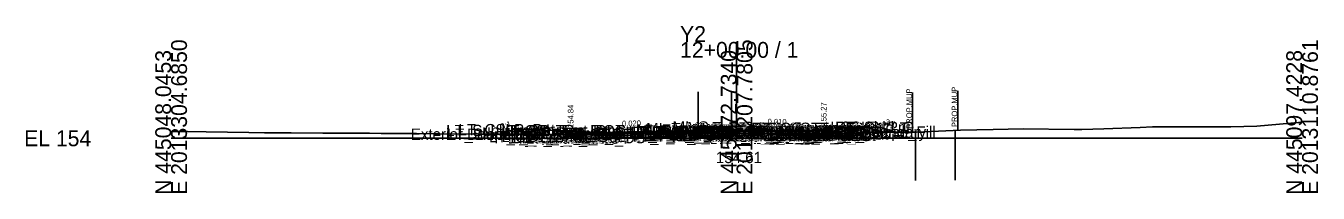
# Model space of a CAD drawing. Extents: x -26 to 203, y -10 to 6017.
# Drawn here: x -25.7 to 202.8, y 3990.3 to 4019.9 of the extents above; entities that cross this region are included whole.
import ezdxf

# ---------------------------------------------------------------- set-up
doc = ezdxf.new("R2010")
doc.units = 0
for name, color, linetype in [('Default', 7, 'Continuous'), ('Exist Cross Section Cell', 7, 'Continuous'), ('Exist XS Center Line Elevation Label', 7, 'Continuous'), ('Exist XS Ground Line', 7, 'Continuous'), ('Prop CMT Conc Surface', 7, 'Continuous'), ('Prop CMT Concrete Structures', 7, 'Continuous'), ('Prop CMT Pvmt Course 1', 7, 'Continuous'), ('Prop CMT Pvmt Course 1 CG', 7, 'Continuous'), ('Prop CMT Pvmt Course 1 Wedge', 7, 'Continuous'), ('Prop CMT Pvmt Course 2', 7, 'Continuous'), ('Prop CMT Pvmt Course 2 Wedge', 7, 'Continuous'), ('Prop CMT Pvmt Course 3', 7, 'Continuous'), ('Prop CMT Pvmt Course 3 Wedge', 7, 'Continuous'), ('Prop CMT Pvmt Surface', 7, 'Continuous'), ('Prop CMT Pvmt Wedge Surface 1', 7, 'Continuous'), ('Prop CMT Pvmt Wedge Surface 2', 7, 'Continuous'), ('Prop CMT Pvmt Wedge Surface 3', 7, 'Continuous'), ('Prop CMT Slope Grass', 7, 'Continuous'), ('Prop CMT Subgrade Earthwork', 7, 'Continuous'), ('Prop XS Earthwork Shape', 7, 'Continuous'), ('Prop XS Hydro Elevations', 7, 'Continuous'), ('Prop XS Label Text', 7, 'Continuous'), ('Prop XS SE Text', 7, 'Continuous'), ('Prop XS Side Slope Text', 7, 'Continuous'), ('Scratch_Level_0', 7, 'Continuous'), ('Scratch_Level_1', 7, 'Continuous'), ('Scratch_Level_3', 7, 'Continuous')]:
    doc.layers.add(name, color=color, linetype=linetype)

msp = doc.modelspace()

# ---------------------------------------------------------------- linework, layer by layer
at = {"layer": 'Exist Cross Section Cell'}
for p, q in [((100, 4000), (100, 4017.03)), ((0, 4000), (100, 4000)), ((100, 4000), (200, 4000))]:
    msp.add_line(p, q, dxfattribs=at)
at = {"layer": 'Exist XS Ground Line'}
msp.add_lwpolyline([(0, 4001.22), (2.89, 4001.18), (6.21, 4001.13), (13.76, 4001.04), (16.53, 4000.98), (21.2, 4000.95), (26.85, 4000.89), (35.05, 4000.88), (37.17, 4000.87), (43.39, 4000.82), (46.66, 4000.81), (47.5, 4000.81), (54.89, 4000.72), (66.1, 4000.74), (69.73, 4000.66), (70.84, 4000.67), (77.18, 4000.71), (83.2, 4000.83), (93.77, 4000.89), (95.2, 4000.9), (95.76, 4000.83), (97.2, 4000.62), (98.31, 4000.62), (100, 4000.61), (107.08, 4000.57), (112.01, 4000.56), (117.01, 4000.56), (118.46, 4000.76), (118.81, 4000.81), (120.45, 4000.9), (125.07, 4001.11), (127.67, 4001.11), (131.82, 4001.11), (139.6, 4001.42), (145.36, 4001.54), (150.7, 4001.69), (159.69, 4001.55), (161.02, 4001.56), (164.92, 4001.68), (171.34, 4001.92), (173.54, 4002.02), (181.66, 4002.04), (187.39, 4002.03), (191.99, 4002.17), (200, 4002.88)], dxfattribs=at)
at = {"layer": 'Prop CMT Conc Surface'}
for points in [[(115.4, 4001.27), (115.41, 4001.77), (115.91, 4001.77)], [(66.15, 4001.43), (61.15, 4001.53)], [(70.65, 4000.84), (70.65, 4001.34), (70.15, 4001.34)], [(70.65, 4000.84), (70.65, 4001.34), (70.15, 4001.34)], [(72.65, 4000.96), (70.65, 4000.84)], [(113.4, 4001.37), (115.4, 4001.27)]]:
    msp.add_lwpolyline(points, dxfattribs=at)
at = {"layer": 'Prop CMT Concrete Structures'}
for p, q in [((93.99, 4001.78), (93.24, 4001.53)), ((98.33, 4001.93), (93.99, 4001.78)), ((99.08, 4001.68), (98.33, 4001.93)), ((99.09, 4001.51), (99.08, 4001.68)), ((93.24, 4001.53), (93.23, 4001.36))]:
    msp.add_line(p, q, dxfattribs=at)
for points in [[(113.4, 4001.37), (115.4, 4001.27), (115.41, 4001.77), (115.91, 4001.77)], [(115.91, 4001.77), (115.9, 4000.76), (113.4, 4000.79)], [(61.15, 4001.19), (61.15, 4001.53)], [(61.15, 4001.53), (66.15, 4001.43)], [(66.15, 4001.09), (61.15, 4001.19)], [(66.15, 4001.43), (66.15, 4001.09)], [(72.65, 4000.96), (70.65, 4000.84), (70.65, 4001.34), (70.15, 4001.34)], [(70.15, 4001.34), (70.15, 4000.32), (72.65, 4000.37)], [(72.65, 4000.37), (72.65, 4000.96)], [(93.23, 4001.36), (99.09, 4001.51)], [(113.4, 4000.79), (113.4, 4001.37)]]:
    msp.add_lwpolyline(points, dxfattribs=at)
at = {"layer": 'Prop CMT Pvmt Course 1'}
for points in [[(93.23, 4001.37), (72.65, 4000.96)], [(72.65, 4000.71), (93.23, 4001.12)], [(72.65, 4000.96), (72.65, 4000.71)], [(93.23, 4001.36), (99.09, 4001.51)], [(93.23, 4001.11), (93.23, 4001.36)], [(93.23, 4001.11), (93.23, 4001.36)], [(99.09, 4001.26), (93.23, 4001.11)], [(93.23, 4001.24), (93.23, 4001.11), (93.23, 4001.11)], [(99.09, 4001.51), (113.4, 4001.37)], [(99.09, 4001.26), (99.09, 4001.51)], [(99.09, 4001.51), (99.09, 4001.26)], [(112.4, 4001.25), (99.09, 4001.39)], [(99.09, 4001.39), (99.09, 4001.26), (99.09, 4001.26)], [(112.4, 4001.13), (112.4, 4001.25)], [(113.4, 4001.12), (112.4, 4001.13)], [(113.4, 4001.37), (113.4, 4001.12)]]:
    msp.add_lwpolyline(points, dxfattribs=at)
at = {"layer": 'Prop CMT Pvmt Course 1 CG'}
for points in [[(72.65, 4000.37), (69.65, 4000.31), (69.31, 3999.97)], [(69.31, 3999.97), (72.65, 4000.04)], [(72.65, 4000.12), (72.65, 4000.37)], [(113.4, 4000.79), (116.4, 4000.76), (116.74, 4000.42)], [(113.4, 4000.54), (113.4, 4000.79)], [(116.74, 4000.42), (113.4, 4000.45)]]:
    msp.add_lwpolyline(points, dxfattribs=at)
at = {"layer": 'Prop CMT Pvmt Course 1 Wedge'}
for points in [[(99.09, 4001.26), (99.09, 4001.39)], [(112.4, 4001.13), (112.01, 4001.13), (107.08, 4001.18), (99.09, 4001.26)], [(100.8, 4001.37), (107.08, 4001.31), (112.01, 4001.26), (112.4, 4001.25)], [(112.4, 4001.25), (112.4, 4001.13)]]:
    msp.add_lwpolyline(points, dxfattribs=at)
at = {"layer": 'Prop CMT Pvmt Course 2'}
for points in [[(93.23, 4001.12), (72.65, 4000.71)], [(72.65, 4000.37), (93.23, 4000.79)], [(72.65, 4000.71), (72.65, 4000.37)], [(93.23, 4001.11), (99.09, 4001.26)], [(93.23, 4000.78), (93.23, 4001.11)], [(99.09, 4000.93), (93.23, 4000.78)], [(99.09, 4001.26), (99.09, 4000.93)], [(112.4, 4000.8), (112.4, 4001.13)], [(112.4, 4001.13), (113.4, 4001.12)], [(113.4, 4000.79), (112.4, 4000.8)], [(113.4, 4001.12), (113.4, 4000.79)]]:
    msp.add_lwpolyline(points, dxfattribs=at)
at = {"layer": 'Prop CMT Pvmt Course 2 Wedge'}
for points in [[(99.09, 4001.26), (107.08, 4001.18), (112.01, 4001.13), (112.4, 4001.13)], [(99.09, 4000.93), (99.09, 4001.26)], [(112.4, 4000.8), (112.01, 4000.8), (107.08, 4000.85), (99.09, 4000.93)], [(112.4, 4001.13), (112.4, 4000.8)]]:
    msp.add_lwpolyline(points, dxfattribs=at)
at = {"layer": 'Prop CMT Pvmt Course 3'}
for points in [[(93.23, 4000.79), (72.65, 4000.37)], [(72.65, 4000.04), (93.23, 4000.45)], [(72.65, 4000.37), (72.65, 4000.04)], [(93.23, 4000.78), (99.09, 4000.93)], [(93.23, 4000.45), (93.23, 4000.78)], [(97.2, 4000.52), (93.23, 4000.45)], [(112.4, 4000.8), (113.4, 4000.79)], [(112.4, 4000.46), (112.4, 4000.8)], [(113.4, 4000.45), (112.4, 4000.46)], [(113.4, 4000.79), (113.4, 4000.45)]]:
    msp.add_lwpolyline(points, dxfattribs=at)
at = {"layer": 'Prop CMT Pvmt Course 3 Wedge'}
for points in [[(99.09, 4000.93), (107.08, 4000.85), (112.01, 4000.8), (112.4, 4000.8)], [(112.4, 4000.56), (112.01, 4000.56), (107.08, 4000.57), (100.8, 4000.61)], [(112.4, 4000.8), (112.4, 4000.56)]]:
    msp.add_lwpolyline(points, dxfattribs=at)
at = {"layer": 'Prop CMT Pvmt Surface'}
for points in [[(93.23, 4001.37), (72.65, 4000.96)], [(93.23, 4001.36), (99.09, 4001.51)], [(99.09, 4001.51), (113.4, 4001.37)]]:
    msp.add_lwpolyline(points, dxfattribs=at)
at = {"layer": 'Prop CMT Pvmt Wedge Surface 1'}
for points in [[(99.09, 4001.51), (99.09, 4001.26), (99.09, 4001.26), (99.09, 4001.39)], [(100.8, 4001.37), (112.4, 4001.25)], [(112.4, 4001.25), (112.4, 4001.13)], [(112.4, 4001.13), (113.4, 4001.12)], [(113.4, 4001.12), (113.4, 4001.37)]]:
    msp.add_lwpolyline(points, dxfattribs=at)
at = {"layer": 'Prop CMT Pvmt Wedge Surface 2'}
for points in [[(99.09, 4001.51), (99.09, 4001.26)], [(99.09, 4001.26), (113.4, 4001.12)], [(113.4, 4001.12), (113.4, 4001.37)]]:
    msp.add_lwpolyline(points, dxfattribs=at)
at = {"layer": 'Prop CMT Pvmt Wedge Surface 3'}
for points in [[(99.09, 4001.51), (99.09, 4000.93)], [(99.09, 4000.93), (113.4, 4000.79)], [(113.4, 4000.79), (113.4, 4001.37)]]:
    msp.add_lwpolyline(points, dxfattribs=at)
at = {"layer": 'Prop CMT Slope Grass'}
for points in [[(115.91, 4001.77), (124.91, 4001.95)], [(124.91, 4001.95), (125.41, 4001.96), (127.96, 4001.11)], [(70.15, 4001.34), (60.65, 4001.53), (58.24, 4000.72)]]:
    msp.add_lwpolyline(points, dxfattribs=at)
at = {"layer": 'Prop CMT Subgrade Earthwork'}
msp.add_line((97.2, 4000.62), (97.2, 4000.52), dxfattribs=at)
for points in [[(113.4, 4000.45), (116.74, 4000.42), (118.14, 4001.81)], [(72.65, 4000.04), (69.31, 3999.97), (67.9, 4001.38)], [(93.23, 4000.45), (72.65, 4000.04)], [(93.23, 4000.45), (97.2, 4000.52)], [(112.4, 4000.46), (112.39, 4000.56)], [(112.4, 4000.46), (113.4, 4000.45)]]:
    msp.add_lwpolyline(points, dxfattribs=at)
at = {"layer": 'Prop XS Earthwork Shape'}
for points in [[(116.89, 4000.56), (118.14, 4001.81), (124.91, 4001.95), (125.41, 4001.96), (127.96, 4001.11), (127.67, 4001.11), (125.07, 4001.11), (120.45, 4000.9), (118.81, 4000.81), (118.46, 4000.76), (117.01, 4000.56)], [(116.89, 4000.56), (118.14, 4001.81), (124.91, 4001.95), (125.41, 4001.96), (127.96, 4001.11), (127.67, 4001.11), (125.07, 4001.11), (120.45, 4000.9), (118.81, 4000.81), (118.46, 4000.76), (117.01, 4000.56)], [(125.41, 4001.96), (127.96, 4001.11), (127.67, 4001.11), (125.07, 4001.11), (120.45, 4000.9), (118.81, 4000.81), (118.46, 4000.76), (117.01, 4000.56), (116.89, 4000.56), (118.14, 4001.81), (124.91, 4001.95)], [(116.89, 4000.56), (118.14, 4001.81), (124.91, 4001.95), (125.41, 4001.96), (127.96, 4001.11), (127.67, 4001.11), (125.07, 4001.11), (120.45, 4000.9), (118.81, 4000.81), (118.46, 4000.76), (117.01, 4000.56)], [(68.6, 4000.68), (67.9, 4001.38), (60.65, 4001.53), (58.24, 4000.72), (66.1, 4000.74)], [(68.6, 4000.68), (67.9, 4001.38), (60.65, 4001.53), (58.24, 4000.72), (66.1, 4000.74)], [(68.6, 4000.68), (67.9, 4001.38), (60.65, 4001.53), (58.24, 4000.72), (66.1, 4000.74)], [(68.6, 4000.68), (67.9, 4001.38), (60.65, 4001.53), (58.24, 4000.72), (66.1, 4000.74)], [(83.2, 4000.83), (93.77, 4000.89), (95.2, 4000.9), (95.76, 4000.83), (97.2, 4000.62), (97.2, 4000.52), (90.38, 4000.39), (72.65, 4000.04), (69.31, 3999.97), (68.6, 4000.68), (69.73, 4000.66), (70.15, 4000.66), (70.15, 4000.32), (72.65, 4000.37), (72.65, 4000.68), (77.18, 4000.71)], [(83.2, 4000.83), (93.77, 4000.89), (95.2, 4000.9), (95.76, 4000.83), (97.2, 4000.62), (97.2, 4000.52), (90.38, 4000.39), (72.65, 4000.04), (69.31, 3999.97), (68.6, 4000.68), (69.73, 4000.66), (70.15, 4000.66), (70.15, 4000.32), (72.65, 4000.37), (72.65, 4000.68), (77.18, 4000.71)], [(83.2, 4000.83), (93.77, 4000.89), (95.2, 4000.9), (95.76, 4000.83), (97.2, 4000.62), (97.2, 4000.52), (90.38, 4000.39), (72.65, 4000.04), (69.31, 3999.97), (68.6, 4000.68), (69.73, 4000.66), (70.15, 4000.66), (70.15, 4000.32), (72.65, 4000.37), (72.65, 4000.68), (77.18, 4000.71)], [(83.2, 4000.83), (93.77, 4000.89), (95.2, 4000.9), (95.76, 4000.83), (97.2, 4000.62), (97.2, 4000.52), (90.38, 4000.39), (72.65, 4000.04), (69.31, 3999.97), (68.6, 4000.68), (69.73, 4000.66), (70.15, 4000.66), (70.15, 4000.32), (72.65, 4000.37), (72.65, 4000.68), (77.18, 4000.71)], [(70.84, 4000.67), (72.65, 4000.68), (72.65, 4000.37), (70.15, 4000.32), (70.15, 4000.66)], [(70.84, 4000.67), (72.65, 4000.68), (72.65, 4000.37), (70.15, 4000.32), (70.15, 4000.66)], [(70.84, 4000.67), (72.65, 4000.68), (72.65, 4000.37), (70.15, 4000.32), (70.15, 4000.66)], [(70.84, 4000.67), (72.65, 4000.68), (72.65, 4000.37), (70.15, 4000.32), (70.15, 4000.66)], [(116.74, 4000.42), (116.89, 4000.56), (112.39, 4000.56), (112.4, 4000.46), (113.4, 4000.45)], [(116.74, 4000.42), (116.89, 4000.56), (112.39, 4000.56), (112.4, 4000.46), (113.4, 4000.45)], [(116.74, 4000.42), (116.89, 4000.56), (112.39, 4000.56), (112.4, 4000.46), (113.4, 4000.45)], [(116.74, 4000.42), (116.89, 4000.56), (112.39, 4000.56), (112.4, 4000.46), (113.4, 4000.45)]]:
    msp.add_lwpolyline(points, close=True, dxfattribs=at)
at = {"layer": 'Prop XS Label Text'}
for p, q in [((131.12, 4008.11), (131.12, 4001.11)), ((139.14, 4008.4), (139.14, 4001.4))]:
    msp.add_line(p, q, dxfattribs=at)
at = {"layer": 'Scratch_Level_1'}
for p, q in [((131.63, 4001.1), (131.63, 3992.52)), ((138.64, 4001.38), (138.64, 3992.63))]:
    msp.add_line(p, q, dxfattribs=at)
at = {"layer": 'Scratch_Level_3'}
for p, q in [((93.23, 4001.36), (93.23, 4008.19)), ((99.09, 4001.51), (99.09, 4008.19))]:
    msp.add_line(p, q, dxfattribs=at)

# ---------------------------------------------------------------- texts
at = {"layer": 'Default'}
msp.add_text('-', height=0.0001, dxfattribs=at).set_placement((0, 4000))
at = {"layer": 'Exist Cross Section Cell'}
for s, p in [('Y2', (90, 4017.03)), ('12+00.00 / 1', (90, 4014.23)), ('EL 154', (-26, 3998.6))]:
    msp.add_text(s, height=2.8, dxfattribs=at).set_placement(p)
for s, p in [('N 445048.0453', (0, 3990)), ('E 2013304.6850', (2.8, 3990)), ('N 445072.7340', (100, 3990)), ('E 2013207.7805', (102.8, 3990)), ('N 445097.4228', (200, 3990)), ('E 2013110.8761', (202.8, 3990))]:
    msp.add_text(s, height=2.8, rotation=90, dxfattribs=at).set_placement(p)
at = {"layer": 'Exist XS Center Line Elevation Label'}
msp.add_text('154.61', height=2, dxfattribs=at).set_placement((96.32, 3995.61))
at = {"layer": 'Prop XS Hydro Elevations'}
for s, p in [('155.27', (115.9, 4002.27)), ('154.84', (71.15, 4001.84))]:
    msp.add_text(s, height=1, rotation=90, dxfattribs=at).set_placement(p)
at = {"layer": 'Prop XS Label Text'}
for p in [(131.02, 4001.68), (139.04, 4001.98)]:
    msp.add_text('PROP.MUP', height=1, rotation=90, dxfattribs=at).set_placement(p)
at = {"layer": 'Prop XS SE Text'}
for s, rotation, p in [('0.020', 1.1458, (79.74, 4002.1)), ('0.010', 359.4271, (105.48, 4002.45))]:
    msp.add_text(s, height=1, rotation=rotation, dxfattribs=at).set_placement(p)
at = {"layer": 'Prop XS Side Slope Text'}
for rotation, p in [(18.4349, (58.45, 4001.59)), (341.5651, (126.17, 4002.5))]:
    msp.add_text('3:1', height=1, rotation=rotation, dxfattribs=at).set_placement(p)
at = {"layer": 'Scratch_Level_0'}
for s, p in [('Exterior Boundary', (42.38, 3999.72)), ('LT_Sub_Trench_Out_DLT', (48.64, 4000.38)), ('LT_Slope_Fill', (48.76, 3999.72)), ('LT_CSLP_Pnt', (50.82, 4000.53)), ('LT_CG_Top_Face', (57.91, 4000.34)), ('LT_CG_Top_BOC', (58.43, 4000.34)), ('LT_CG_Top_Gut', (58.88, 3999.84)), ('LT_PV2_OEOT', (62.82, 3999.71)), ('LT_PV1_OEOT', (63.39, 3999.96)), ('LT_PV2_IEEOP', (80.33, 4000.06)), ('LT_PV1_IEEOP', (80.9, 4000.19)), ('LT_PV2_PGL1', (81.26, 4000.06)), ('LT_PV3_PGL1', (81.26, 3999.73)), ('LT_PV2_PGL', (81.59, 4000.06)), ('LT_PV1_PGL', (82.16, 4000.31)), ('MI_Face In', (82.28, 4000.48)), ('MI_Top In', (83.99, 4000.73)), ('LT_PV2_OEEOP', (84.51, 4000.16)), ('LT_PV3_OEEOP', (84.51, 3999.82)), ('LT_PV1_OEEOP', (85.08, 4000.28)), ('MI_Crown', (88.66, 4001)), ('RT_PV_IEEOP_EG', (88.94, 3999.61)), ('RT_PV2_IEEOP', (90.7, 4000.25)), ('RT_PV3_IEEOP', (90.7, 3999.91)), ('MI_Face Out', (91.05, 4000.66)), ('MI_Top Out', (91.26, 4000.91)), ('RT_PV1_IEEOP', (91.27, 4000.37)), ('RT_PV2_PGL1', (91.63, 4000.25)), ('RT_PV3_PGL1', (91.63, 3999.91)), ('RT_PV2_PGL', (91.96, 4000.25)), ('RT_PV3_PGL', (91.96, 3999.91)), ('RT_PV4_PGL', (91.96, 3999.58)), ('MI_Bot Out', (92.06, 4000.5)), ('RT_PV1_PGL', (92.53, 4000.5)), ('RT_PV_Sub_Tie_Out', (97.28, 3999.56)), ('RT_Sub_Trench_Out_DLT', (98.48, 4000.81)), ('RT_Sub_OEOT_CG', (100.73, 3999.54)), ('RT_PV2_OEEOP', (101.66, 4000.13)), ('RT_PV3_OEEOP', (101.66, 3999.8)), ('RT_PV1_OEEOP', (102.23, 4000.25)), ('RT_CG_Top_Face', (102.62, 4000.77)), ('RT_CG1_Shelf_Out', (102.91, 3999.76)), ('RT_CG_Bot_IE', (103.27, 3999.79)), ('RT_PV2_OEOT', (103.53, 4000.12)), ('RT_PV3_OEOT', (103.53, 3999.79)), ('RT_CG_Top_Gut', (103.59, 4000.27)), ('RT_PV1_OEOT', (104.1, 4000.37)), ('RT_CG_Top_BOC', (104.14, 4000.77)), ('RT_CG_Bot_BOC', (104.17, 3999.76)), ('RT_Sub_OEOP', (106.72, 3999.5)), ('Exterior Boundary', (112.1, 4000.11)), ('RT_Shld_O', (117.44, 4000.95)), ('CSLP_Pnt', (118.27, 4000.96)), ('RT_Slope_Fill', (118.43, 4000.11)), ('LT_CG1_Shelf_Out', (56.2, 3999.31)), ('LT_CG_Bot_BOC', (58.46, 3999.32)), ('LT_Sub_OEOP', (59.5, 3999.06)), ('LT_Sub_OEOT_CG', (60.02, 3999.12)), ('LT_CG_Bot_IE', (62.56, 3999.37)), ('LT_Sub_OEOT', (62.73, 3999.04)), ('LT_PV3_OEOT', (62.82, 3999.37)), ('LT_PV4_PGL', (81.59, 3999.39)), ('LT_Sub_OEEOP', (84.42, 3999.49)), ('RT_PV_EG_TestPt', (92.96, 3999.57)), ('RT_PV_OEEOP_EG', (99.9, 3999.56)), ('RT_Sub_OEEOP', (101.57, 3999.46)), ('RT_Sub_OEOT', (103.44, 3999.45))]:
    msp.add_text(s, height=2, dxfattribs=at).set_placement(p)

doc.saveas('drawing.dxf')
